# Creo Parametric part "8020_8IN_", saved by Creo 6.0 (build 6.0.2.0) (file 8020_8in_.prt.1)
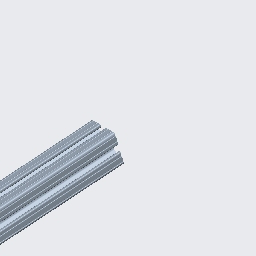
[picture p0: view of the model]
Units: Inch lbm Second (Pro/E Default); INCH, POUND, SECS

Created from: INLBS_PART_SOLID.PRT

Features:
  1. datum plane "RIGHT"
  2. datum plane "TOP"
  3. datum plane "FRONT"
  4. coordinate system
  5. curve "Project 1"
  6. sketch "Sketch 2"
  7. extrusion "Extrude 1"

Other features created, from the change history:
  sketch "Sketch 1"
